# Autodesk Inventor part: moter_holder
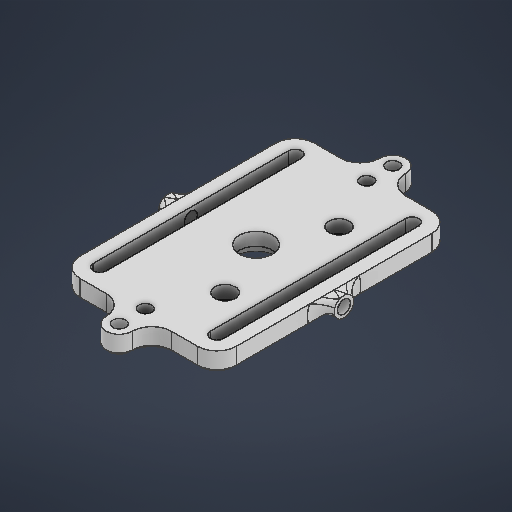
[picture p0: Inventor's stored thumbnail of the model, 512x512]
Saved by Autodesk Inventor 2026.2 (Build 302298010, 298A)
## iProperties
Created: 2026-05
Part Number: moter_holder
Material: 일반
Document SubType Name: Modeling
Designer: work
Density: 1 g/cm^3
Appearance: 기본값
Author: work
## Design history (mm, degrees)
sketch "스케치1" dims "d9" = 20
  geometry: L1 (0, 17.5)-(0, -17.5); L2 (8, 0)-(0, 0); L3 (8, 30)-(8, -30); L4 (26, 30)-(-10, 30); L5 (-10, 30)-(-10, -30); L6 (-10, -30)-(26, -30); L7 (26, -30)-(26, 30); L8 (26, 30)-(26, -30); L9 (24, 30)-(24, -30); L10 (28, -30)-(28, 30); L11 (-10, 30)-(-10, -30); L12 (-12, 30)-(-12, -30); L13 (-8, -30)-(-8, 30); L14 (-2, -34)-(-10, -34); L15 (-10, -34)-(-10, 34); L16 (-10, 34)-(-2, 34); L17 (-2, 34)-(-2, -34); L18 (-16, 36)-(32, 36); L19 (32, 36)-(32, -36); L20 (32, -36)-(-16, -36); L21 (-16, -36)-(-16, 36); L22 (-16, 36)-(32, -36); L23 (32, 36)-(-16, -36); C1 r 2.7 at (8, 0); C2 r 2 at (0, 17.5); C3 r 2 at (0, -17.5); A1 r 2 centre (26, 30) between (28, 30) and (24, 30); A2 r 2 centre (26, -30) between (24, -30) and (28, -30); A3 r 2 centre (-10, 30) between (-8, 30) and (-12, 30); A4 r 2 centre (-10, -30) between (-12, -30) and (-8, -30); 5 further points
  constraints: 50 end point, 11 midpoint, 9 parallel, 8 point on circle, 8 tangent, 7 centre point, 4 horizontal, 3 coincident, 3 perpendicular, 2 collinear, 1 horizontal alignment, 1 vertical, 2 other
  dimensions: "d0" = 5.4 diameter of C1; "d1" = 8 distance of L2.start L2.end; "d2" = 35 distance of L1.start L1.end; "d3" = 4 diameter of C2; "d4" = 4 diameter of C3; "d5" = 60 distance of L3.start L3.end; "d6" = 36 distance between parallel lines of L5 L7; "d7" = 4 diameter of A2; "d8" = 4 diameter of A4; "d10" = 4 distance between parallel lines of L4 L16; "d11" = 6 distance between parallel lines of L19 L8; "d12" = 6 distance between parallel lines of L20 L6
extrude "돌출1" new body sketch "스케치1" distance "d13" = 6; taper "d14" = 0 deg
sketch "스케치2"
  geometry: L1 (16, 36)-(-32, 36) reference; L2 (-32, 36)-(-32, -36) reference; L3 (-32, -36)-(16, -36) reference; L4 (16, -36)-(16, 36) reference; L5 (8, -30)-(8, 30) reference; L6 (12, 30)-(12, -30) reference; L7 (-28, -30)-(-28, 30) reference; L8 (-24, 30)-(-24, -30) reference; C1 r 2.7 at (-8, 0) reference; C2 r 2 at (0, -17.5) reference; C3 r 2 at (0, 17.5) reference; C4 r 3.15 at (0, -17.5); C5 r 3.1 at (0, 17.5); C6 r 5.1 at (-8, 0); A1 r 2 centre (10, -30) between (8, -30) and (12, -30) reference; A2 r 2 centre (10, 30) between (12, 30) and (8, 30) reference; A3 r 2 centre (-26, -30) between (-28, -30) and (-24, -30) reference; A4 r 2 centre (-26, 30) between (-24, 30) and (-28, 30) reference; 1 further point
  constraints: 3 centre point, 3 coincident
  dimensions: "d15" = 6.3 diameter of C4; "d16" = 6.2 diameter of C5; "d22" = 10.2 diameter of C6
extrude "돌출2" cut sketch "스케치2" distance "d17" = 4; taper "d18" = 0 deg
sketch "스케치3"
  geometry: L1 (16, -36)-(-32, -36) reference; L2 (16, 36)-(16, -36) reference; L3 (-32, 36)-(16, 36) reference; L4 (-32, -36)-(-32, 36) reference; L5 (12, -30)-(12, 30) reference; L6 (8, 30)-(8, -30) reference; L7 (-24, -30)-(-24, 30) reference; L8 (-28, 30)-(-28, -30) reference; C1 r 2.7 at (-8, 0) reference; C2 r 2 at (0, 17.5) reference; C3 r 2 at (0, -17.5) reference; C4 r 6 at (-8, 0); A1 r 2 centre (10, 30) between (12, 30) and (8, 30) reference; A2 r 2 centre (10, -30) between (8, -30) and (12, -30) reference; A3 r 2 centre (-26, 30) between (-24, 30) and (-28, 30) reference; A4 r 2 centre (-26, -30) between (-28, -30) and (-24, -30) reference; 1 further point
  constraints: 1 centre point, 1 coincident
  dimensions: "d23" = 12 diameter of C4
extrude "돌출3" cut sketch "스케치3" distance "d24" = 2; taper "d25" = 0 deg
sketch "스케치4"
  geometry: L1 (16, 36)-(-32, 36) reference; L2 (-32, 36)-(-32, -36) reference; L3 (-32, -36)-(16, -36) reference; L4 (16, -36)-(16, 36) reference; L5 (8, -30)-(8, 30) reference; L6 (12, 30)-(12, -30) reference; L7 (-28, -30)-(-28, 30) reference; L8 (-24, 30)-(-24, -30) reference; L9 (-8, 42)-(-8, -42); L10 (-12, 42)-(-12, -42); L11 (-4, -42)-(-4, 42); C1 r 3.1 at (0, 17.5) reference; C2 r 3.15 at (0, -17.5) reference; C3 r 5.1 at (-8, 0) reference; C4 r 2 at (-8, 42); C5 r 2 at (-8, -42); A1 r 2 centre (10, -30) between (8, -30) and (12, -30) reference; A2 r 2 centre (10, 30) between (12, 30) and (8, 30) reference; A3 r 2 centre (-26, -30) between (-28, -30) and (-24, -30) reference; A4 r 2 centre (-26, 30) between (-24, 30) and (-28, 30) reference; A5 r 4 centre (-8, 42) between (-4, 42) and (-12, 42); A6 r 4 centre (-8, -42) between (-12, -42) and (-4, -42); 5 further points
  constraints: 8 end point, 4 centre point, 4 point on circle, 4 tangent, 2 coincident, 1 midpoint, 1 parallel, 1 vertical
  dimensions: "d26" = 8 diameter of A6; "d27" = 4 diameter of C4; "d28" = 4 diameter of C5; "d29" = 6 distance from line of L3 C5.centre
extrude "돌출4" join sketch "스케치4" stored distance "d30" = 2; taper "d31" = 0 deg
fillet "모깎기1" dims "d32" = 6
chamfer "모따기2" distance "d33" = 1; stored, may be unused: second distance "d34" = 2, angle "d35" = 45 deg
sketch "스케치5"
  geometry: L1 (-24, -30)-(-24, 30) reference; L2 (-28, 30)-(-28, -30) reference; L3 (12, -30)-(12, 30) reference; L4 (8, 30)-(8, -30) reference; L5 (10, -35)-(2, -35) reference; L6 (15, 30)-(15, -30) reference; L7 (2, 35)-(10, 35) reference; L8 (-26, 35)-(-18, 35) reference; L9 (-31, -30)-(-31, 30) reference; L10 (-18, -35)-(-26, -35) reference; L11 (12, 0)-(-28, 0); L12 (-8, 42)-(-8, -42); C1 r 2 at (0, -17.5) reference; C2 r 2 at (0, 17.5) reference; C3 r 6 at (-8, 0) reference; C4 r 2 at (-8, 42) reference; C5 r 2 at (-8, -42) reference; C6 r 2 at (-8, -34); C7 r 2 at (-8, 34); A1 r 2 centre (-26, 30) between (-24, 30) and (-28, 30) reference; A2 r 2 centre (-26, -30) between (-28, -30) and (-24, -30) reference; A3 r 2 centre (10, 30) between (12, 30) and (8, 30) reference; A4 r 2 centre (10, -30) between (8, -30) and (12, -30) reference; A5 r 5 centre (10, -30) between (10, -35) and (15, -30) reference; A6 r 5 centre (10, 30) between (15, 30) and (10, 35) reference; A7 r 7 centre (2, 42) between (-5, 42) and (2, 35) reference; A8 r 3 centre (-8, 42) between (-5, 42) and (-11, 42) reference; A9 r 7 centre (-18, 42) between (-18, 35) and (-11, 42) reference; A10 r 5 centre (-26, 30) between (-26, 35) and (-31, 30) reference; A11 r 5 centre (-26, -30) between (-31, -30) and (-26, -35) reference; A12 r 7 centre (-18, -42) between (-11, -42) and (-18, -35) reference; A13 r 3 centre (-8, -42) between (-11, -42) and (-5, -42) reference; A14 r 7 centre (2, -42) between (2, -35) and (-5, -42) reference; 1 further point
  constraints: 4 end point, 2 centre point, 2 midpoint, 1 point on line, 1 symmetric about line, 1 vertical, 1 other
  dimensions: "d36" = 4 diameter of C6; "d37" = 8 distance of C5.centre C6.centre
extrude "돌출5" cut sketch "스케치5" extent not by distance; stored distance "d38" = 0; taper "d39" = 0 deg
sketch "스케치6"
  geometry: L1 (60, -5)-(0, -5) reference; L2 (60, 0)-(60, -5) reference; L3 (0, 0)-(60, 0) reference; L4 (0, -5)-(0, 0) reference; L5 (0, 0)-(60, 0) reference; L6 (0, -6)-(60, -6) reference; L7 (30, -3)-(30, -6); C1 r 3 at (30, -3); 2 further points
  constraints: 2 end point, 1 centre point, 1 tangent, 1 vertical
  dimensions: "d40" = 6 diameter of C1
  node "투영된 루프5"
extrude "돌출6" join sketch "스케치6" stored distance "d41" = 10; taper "d42" = 0 deg
extrude "돌출7" join sketch "스케치6" distance "d43" = 3; taper "d44" = 0 deg
fillet "모깎기2" dims "d45" = 6
fillet "모깎기3" dims "d46" = 2
sketch "스케치7"
  geometry: C1 r 2 at (30, -3); A1 r 3 centre (30, -3) between (27.208, -1.902) and (27.208, -4.097) reference; A2 r 3 centre (30, -3) between (27.208, -4.097) and (32.792, -4.097) reference; A3 r 3 centre (30, -3) between (32.792, -4.097) and (32.792, -1.902) reference; A4 r 3 centre (30, -3) between (32.792, -1.902) and (31.239, -0.268) reference; A5 r 3 centre (30, -3) between (31.239, -0.268) and (28.761, -0.268) reference; A6 r 3 centre (30, -3) between (28.761, -0.268) and (27.208, -1.902) reference; 1 further point
  constraints: 1 centre point, 1 coincident
  dimensions: "d47" = 4 diameter of C1
extrude "돌출8" cut sketch "스케치7" stored distance "d48" = 4 (= d47); taper "d49" = 0 deg
node "작업 평면1"
node "솔리드1"
mirror "미러1"
node "투영된 루프1"
node "투영된 루프2"
node "투영된 루프3"
node "투영된 루프4"
node "투영된 루프6"
